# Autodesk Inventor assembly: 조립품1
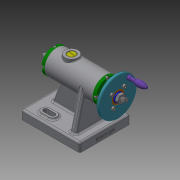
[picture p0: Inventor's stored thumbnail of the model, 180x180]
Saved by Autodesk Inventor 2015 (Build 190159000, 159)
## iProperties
Created: 2022-06
Part Number: 조립품1
Document SubType Name: Assembly
Designer: 10462
Author: 10462
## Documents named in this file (18)
- C:\Users\10462\Desktop\720606V1010\조립품.iam
- C:\Users\10462\Desktop\720606V1010\Ű 4 x 4 x 10.ipt
- C:\Users\10462\Desktop\720606V1010\나사.ipt
- C:\Users\10462\Desktop\720606V1010\나사축.ipt
- C:\Users\10462\Desktop\720606V1010\너트 M8.ipt
- C:\Users\10462\Desktop\720606V1010\돌림판.ipt
- C:\Users\10462\Desktop\720606V1010\멈춤나사 M3.ipt
- C:\Users\10462\Desktop\720606V1010\볼트 M3.ipt
- C:\Users\10462\Desktop\720606V1010\부시.ipt
- C:\Users\10462\Desktop\720606V1010\본체.ipt
- C:\Users\10462\Desktop\720606V1010\센터.ipt
- C:\Users\10462\Desktop\720606V1010\센터홀더.ipt
- C:\Users\10462\Desktop\720606V1010\슬리브.ipt
- C:\Users\10462\Desktop\720606V1010\와셔.ipt
- C:\Users\10462\Desktop\720606V1010\중공축.ipt
- C:\Users\10462\Desktop\720606V1010\커버.ipt
- C:\Users\10462\Desktop\720606V1010\플랜지.ipt
- C:\Users\10462\Desktop\720606V1010\핸들.ipt
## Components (3 placed, 3 different names)
1. Ű 4 x 4 x 10:1
2. 플랜지:1
3. 핸들:1 — 플러쉬:4
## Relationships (1: Flush 1)
- 플러쉬:4 [Flush]: 핸들:1
